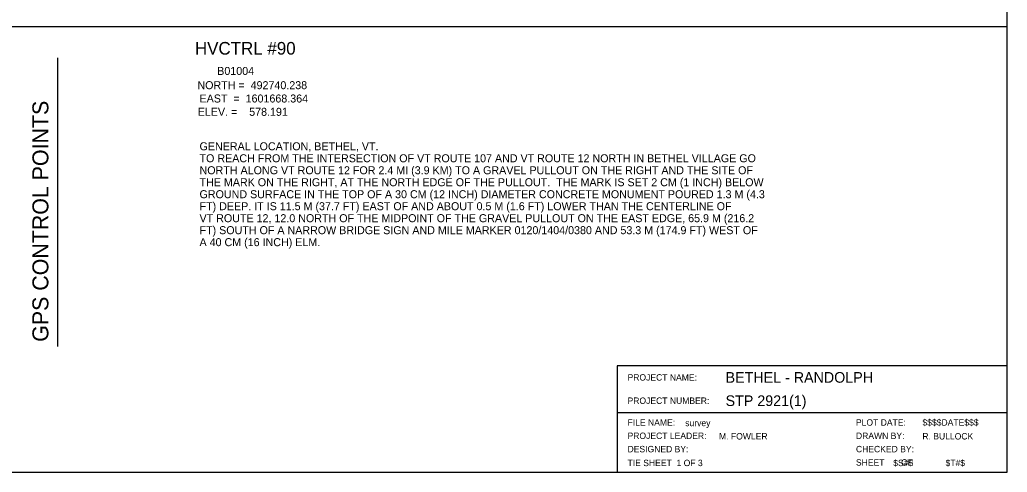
# Model space of a CAD drawing. Extents: x 1598730 to 1599370, y 501440 to 502728.
# Drawn here: x 1598999.2 to 1599369.5, y 502307.8 to 502477.7 of the extents above; entities that cross this region are included whole.
import ezdxf

# ---------------------------------------------------------------- set-up
doc = ezdxf.new("R2010")
doc.units = 0
for name, color, linetype in [('Default', 7, 'Continuous'), ('NBL1', 7, 'Continuous'), ('NBL2', 7, 'Continuous')]:
    doc.layers.add(name, color=color, linetype=linetype)

msp = doc.modelspace()

# ---------------------------------------------------------------- linework, layer by layer
at = {"layer": 'NBL1'}
msp.add_line((1599223.28, 502330.33), (1599369.53, 502330.33), dxfattribs=at)
msp.add_lwpolyline([(1598729.53, 502307.83), (1599369.53, 502307.83), (1599369.53, 502727.83), (1598729.53, 502727.83)], close=True, dxfattribs=at)
msp.add_lwpolyline([(1599369.53, 502347.83), (1599223.28, 502347.83), (1599223.28, 502307.83)], dxfattribs=at)
at = {"layer": 'NBL2'}
for p, q in [((1598729.53, 502475.17), (1599369.53, 502475.17)), ((1599013.47, 502355.08), (1599013.47, 502463.42))]:
    msp.add_line(p, q, dxfattribs=at)

# ---------------------------------------------------------------- texts
at = {"layer": 'Default'}
for s, p in [('GENERAL LOCATION, BETHEL, VT.', (1599066.65, 502428.73)), ('TO REACH FROM THE INTERSECTION OF VT ROUTE 107 AND VT ROUTE 12 NORTH IN BETHEL VILLAGE GO ', (1599066.65, 502424.23)), ('NORTH ALONG VT ROUTE 12 FOR 2.4 MI (3.9 KM) TO A GRAVEL PULLOUT ON THE RIGHT AND THE SITE OF ', (1599066.65, 502419.73)), ('THE MARK ON THE RIGHT, AT THE NORTH EDGE OF THE PULLOUT.  THE MARK IS SET 2 CM (1 INCH) BELOW ', (1599066.65, 502415.23)), ('GROUND SURFACE IN THE TOP OF A 30 CM (12 INCH) DIAMETER CONCRETE MONUMENT POURED 1.3 M (4.3 ', (1599066.65, 502410.73)), ('FT) DEEP. IT IS 11.5 M (37.7 FT) EAST OF AND ABOUT 0.5 M (1.6 FT) LOWER THAN THE CENTERLINE OF ', (1599066.65, 502406.23)), ('VT ROUTE 12, 12.0 NORTH OF THE MIDPOINT OF THE GRAVEL PULLOUT ON THE EAST EDGE, 65.9 M (216.2 ', (1599066.65, 502401.73)), ('FT) SOUTH OF A NARROW BRIDGE SIGN AND MILE MARKER 0120/1404/0380 AND 53.3 M (174.9 FT) WEST OF ', (1599066.65, 502397.23)), ('A 40 CM (16 INCH) ELM.', (1599066.65, 502392.73))]:
    msp.add_text(s, height=3, dxfattribs=at).set_placement(p)
at = {"layer": 'NBL1'}
for s, height, p in [('BETHEL - RANDOLPH         ', 4, (1599263.92, 502341.46)), ('PROJECT NAME:', 2.4, (1599227.15, 502342.26)), ('PROJECT NUMBER:', 2.4, (1599227.15, 502333.51)), ('STP 2921(1)               ', 4, (1599263.92, 502332.71)), ('FILE NAME:', 2.4, (1599227.15, 502325.34)), ('survey                    ', 2.4, (1599248.78, 502325.14)), ('PLOT DATE:', 2.4, (1599312.8, 502325.34)), ('$$$$DATE$$$', 2.4, (1599337.73, 502325.34)), ('PROJECT LEADER:', 2.4, (1599227.15, 502320.34)), ('DRAWN BY:', 2.4, (1599312.8, 502320.34)), ('M. FOWLER           ', 2.4, (1599261.47, 502320.14)), ('R. BULLOCK   ', 2.4, (1599337.7, 502320.14)), ('DESIGNED BY:', 2.4, (1599227.15, 502315.34)), ('CHECKED BY:', 2.4, (1599312.8, 502315.34)), ('TIE SHEET  1 OF 3                 ', 2.4, (1599227.15, 502310.14)), ('SHEET       OF', 2.4, (1599312.8, 502310.34)), ('$S#$ ', 2.4, (1599326.78, 502310.14)), ('$T#$   ', 2.4, (1599346.4, 502310.14))]:
    msp.add_text(s, height=height, dxfattribs=at).set_placement(p)
at = {"layer": 'NBL2'}
for s, height, p in [('     HVCTRL #90    ', 4.75, (1599056.09, 502464.64)), ('        B01004       ', 3, (1599064.37, 502457.02)), ('NORTH =  492740.238 ', 3, (1599065.86, 502451.67)), ('EAST  =  1601668.364', 3, (1599066.65, 502446.67)), ('ELEV. =    578.191  ', 3, (1599065.97, 502441.67))]:
    msp.add_text(s, height=height, dxfattribs=at).set_placement(p)
msp.add_text('GPS CONTROL POINTS', height=6, rotation=90, dxfattribs=at).set_placement((1599009.97, 502356.83))

doc.saveas('drawing.dxf')
